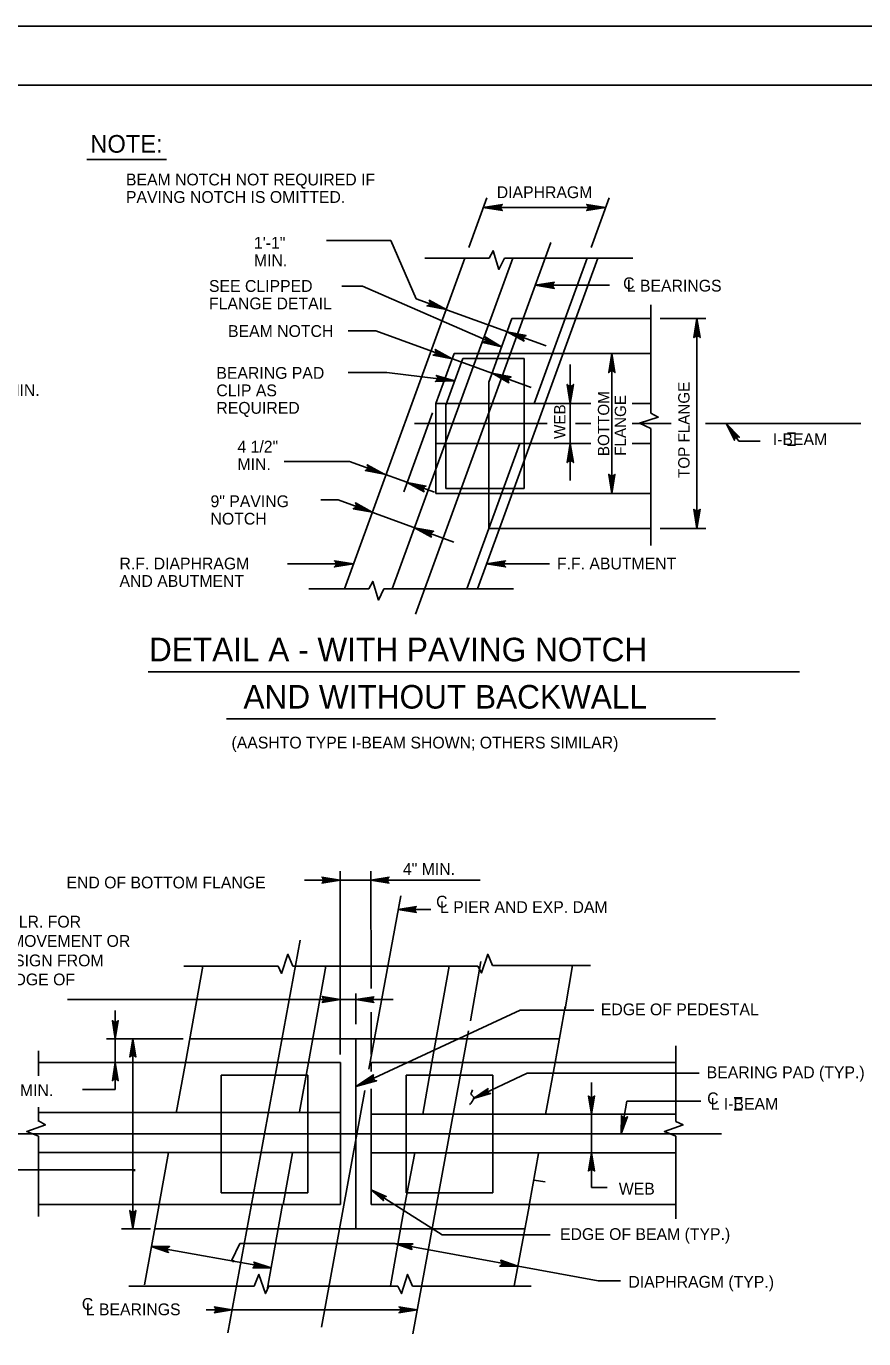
# Model space of a CAD drawing. Extents: x 639028 to 640031, y 298558 to 299746.
# Drawn here: x 639459.6 to 639672.4, y 299412.7 to 299746.3 of the extents above; entities that cross this region are included whole.
import ezdxf

# ---------------------------------------------------------------- set-up
doc = ezdxf.new("R2010")
doc.units = 0
doc.layers.add('1', color=7, linetype='Continuous')
doc.layers.add('PLT-BNDY', color=7, linetype='Continuous')

msp = doc.modelspace()

# ---------------------------------------------------------------- linework, layer by layer
at = {"layer": '1'}
for p, q in [((639067.87, 299731.33), (639853.87, 299731.33)), ((639474.99, 299712.43), (639495.21, 299712.43)), ((639576.61, 299702.74), (639572.01, 299690.11)), ((639607.69, 299702.74), (639603.09, 299690.11)), ((639575.71, 299700.26), (639606.79, 299700.26)), ((639552.19, 299691.84), (639535.85, 299691.84)), ((639558.68, 299677.08), (639552.19, 299691.84)), ((639592.91, 299691.39), (639558.52, 299596.93)), ((639571.02, 299687.39), (639540.43, 299603.33)), ((639583.18, 299687.39), (639552.59, 299603.33)), ((639577.2, 299687.39), (639560.84, 299687.39)), ((639613.7, 299687.39), (639581.08, 299687.39)), ((639602.1, 299687.39), (639596.51, 299672.03)), ((639604.81, 299687.39), (639599.22, 299672.03)), ((639545.05, 299680.29), (639539.8, 299680.29)), ((639580.37, 299664.8), (639545.05, 299680.29)), ((639588.93, 299680.48), (639607.74, 299680.48)), ((639591.71, 299665.06), (639558.68, 299677.08)), ((639618.26, 299675.52), (639618.26, 299647.98)), ((639583, 299672.03), (639577.1, 299655.82)), ((639599.22, 299672.03), (639579.8, 299618.69)), ((639583, 299672.03), (639618.26, 299672.03)), ((639596.51, 299672.03), (639588.66, 299650.44)), ((639620.61, 299672.03), (639632.25, 299672.03)), ((639630, 299672.03), (639630, 299618.69)), ((639548.37, 299668.87), (639541.42, 299668.87)), ((639587.86, 299654.5), (639548.37, 299668.87)), ((639563.65, 299650.44), (639568.28, 299663.14)), ((639566.19, 299649.99), (639570.52, 299661.87)), ((639579.76, 299663.14), (639568.28, 299663.14)), ((639570.52, 299661.87), (639586.11, 299661.87)), ((639579.76, 299663.14), (639618.26, 299663.14)), ((639586.11, 299661.87), (639586.11, 299628.85)), ((639608.37, 299663.14), (639608.37, 299627.58)), ((639551.17, 299658.35), (639541.42, 299658.35)), ((639568.46, 299656.22), (639551.17, 299658.35)), ((639597.82, 299660.36), (639597.82, 299630.83)), ((639577.1, 299655.82), (639577.1, 299618.69)), ((639562.8, 299648.1), (639555.48, 299627.99)), ((639563.65, 299650.44), (639563.65, 299627.58)), ((639563.65, 299650.44), (639577.1, 299650.44)), ((639566.19, 299649.99), (639566.19, 299628.85)), ((639577.1, 299650.44), (639603.04, 299650.44)), ((639613.53, 299650.44), (639618.26, 299650.44)), ((639558.27, 299645.36), (639591.97, 299645.36)), ((639599.13, 299645.36), (639603.04, 299645.36)), ((639613.53, 299645.36), (639623.46, 299645.36)), ((639632.13, 299645.36), (639671.62, 299645.36)), ((639640.66, 299640.86), (639637.53, 299645.23)), ((639618.26, 299644.11), (639618.26, 299614.34)), ((639653.03, 299642.86), (639655.03, 299642.86)), ((639563.65, 299640.28), (639577.1, 299640.28)), ((639577.1, 299640.28), (639603.04, 299640.28)), ((639584.96, 299640.28), (639577.1, 299618.69)), ((639613.53, 299640.28), (639618.26, 299640.28)), ((639640.66, 299640.86), (639646.03, 299640.86)), ((639653.03, 299639.86), (639655.03, 299639.86)), ((639541.73, 299635.71), (639525.15, 299635.71)), ((639563.28, 299627.86), (639541.73, 299635.71)), ((639566.19, 299628.85), (639586.11, 299628.85)), ((639538.85, 299625.93), (639534.43, 299625.93)), ((639568.26, 299615.22), (639538.85, 299625.93)), ((639577.1, 299627.58), (639563.65, 299627.58)), ((639577.1, 299627.58), (639618.26, 299627.58)), ((639577.1, 299618.69), (639571.51, 299603.33)), ((639579.8, 299618.69), (639574.21, 299603.33)), ((639577.1, 299618.69), (639618.26, 299618.69)), ((639620.61, 299618.69), (639632.25, 299618.69)), ((639525.95, 299609.66), (639542.73, 299609.66)), ((639576.52, 299609.66), (639592.52, 299609.66)), ((639546.61, 299603.33), (639531.42, 299603.33)), ((639583.42, 299603.33), (639550.48, 299603.33)), ((639490.55, 299582.26), (639656.07, 299582.26)), ((639510.46, 299570.26), (639634.68, 299570.26)), ((639539.31, 299531.55), (639539.36, 299484.93)), ((639547.16, 299531.56), (639547.19, 299501.72)), ((639530.31, 299529.3), (639574.91, 299529.3)), ((639554.72, 299525.31), (639546.63, 299481.25)), ((639554.09, 299521.81), (639562.34, 299521.81)), ((639529.17, 299514.06), (639510.79, 299414.2)), ((639575.08, 299508.56), (639572.42, 299493.49)), ((639499.59, 299507.43), (639523.59, 299507.43)), ((639504.42, 299507.43), (639500.08, 299482.81)), ((639574.34, 299507.43), (639527.34, 299507.43)), ((639535.72, 299507.43), (639531.27, 299482.93)), ((639567.06, 299507.43), (639562.63, 299482.93)), ((639602.97, 299507.56), (639578.09, 299507.56)), ((639598.34, 299507.56), (639596.47, 299496.56)), ((639470.08, 299498.93), (639539.35, 299498.93)), ((639539.35, 299498.93), (639552.83, 299498.93)), ((639543.34, 299500.44), (639543.34, 299492.65)), ((639482.22, 299488.93), (639482.22, 299496.14)), ((639585.05, 299496.22), (639543.34, 299476.79)), ((639547.2, 299495.74), (639547.21, 299484.94)), ((639585.05, 299496.22), (639603.8, 299496.22)), ((639596.47, 299497.18), (639593.93, 299482.93)), ((639479.95, 299488.93), (639499.47, 299488.93)), ((639482.22, 299482.81), (639482.22, 299488.93)), ((639486.66, 299440.68), (639486.66, 299488.93)), ((639532.47, 299488.93), (639501.16, 299488.93)), ((639532.47, 299488.93), (639563.71, 299488.93)), ((639543.34, 299440.68), (639543.34, 299488.93)), ((639571.93, 299490.95), (639557.77, 299413.94)), ((639563.71, 299488.93), (639594.97, 299488.93)), ((639462.72, 299485.93), (639462.72, 299479.56)), ((639624.59, 299487.18), (639624.59, 299467.93)), ((639462.72, 299482.93), (639539.47, 299482.93)), ((639482.22, 299476.09), (639482.22, 299482.81)), ((639500.08, 299482.81), (639497.68, 299470.06)), ((639529, 299470.43), (639531.27, 299482.93)), ((639539.47, 299446.81), (639539.47, 299482.93)), ((639547.22, 299482.93), (639624.59, 299482.93)), ((639547.22, 299480.6), (639547.22, 299482.93)), ((639562.63, 299482.93), (639560.36, 299469.81)), ((639593.93, 299482.93), (639591.52, 299469.68)), ((639531.11, 299479.68), (639509.11, 299479.68)), ((639509.11, 299479.68), (639509.11, 299449.81)), ((639531.11, 299449.81), (639531.11, 299479.68)), ((639556.12, 299479.68), (639578.12, 299479.68)), ((639556.12, 299449.81), (639556.12, 299479.68)), ((639586.88, 299480.18), (639573.19, 299473.8)), ((639578.12, 299479.68), (639578.12, 299449.81)), ((639586.88, 299480.18), (639630.59, 299480.18)), ((639473.85, 299476.09), (639482.22, 299476.09)), ((639545.64, 299475.83), (639534.59, 299415.68)), ((639547.22, 299446.81), (639547.22, 299476.2)), ((639603.22, 299477.82), (639603.22, 299451.14)), ((639462.72, 299471.59), (639462.72, 299467.93)), ((639612.22, 299473.06), (639610.72, 299464.81)), ((639612.22, 299473.06), (639630.97, 299473.06)), ((639639.47, 299473.93), (639641.47, 299473.93)), ((639539.47, 299470.18), (639462.72, 299470.18)), ((639624.59, 299469.81), (639547.22, 299469.81)), ((639639.47, 299470.93), (639641.47, 299470.93)), ((639454.72, 299464.81), (639520.11, 299464.81)), ((639520.11, 299464.81), (639543.61, 299464.81)), ((639543.61, 299464.81), (639567.12, 299464.81)), ((639567.12, 299464.81), (639636.22, 299464.81)), ((639462.72, 299464.18), (639462.72, 299443.81)), ((639624.59, 299464.18), (639624.59, 299443.15)), ((639539.47, 299460.06), (639462.72, 299460.06)), ((639493.35, 299446.93), (639495.73, 299460.06)), ((639524.84, 299446.81), (639527.22, 299459.93)), ((639624.59, 299459.93), (639547.22, 299459.93)), ((639555.81, 299446.81), (639558.33, 299459.93)), ((639589.74, 299459.81), (639587.43, 299447.06)), ((639434.55, 299455.68), (639486.66, 299455.68)), ((639588.59, 299453.06), (639591.47, 299452.56)), ((639509.11, 299449.81), (639531.11, 299449.81)), ((639547.22, 299450.53), (639565.3, 299439.12)), ((639578.12, 299449.81), (639556.12, 299449.81)), ((639603.22, 299451.14), (639607.2, 299451.14)), ((639539.47, 299446.81), (639462.72, 299446.81)), ((639493.33, 299446.81), (639489.67, 299426.43)), ((639524.68, 299446.81), (639520.82, 299425.15)), ((639624.59, 299446.81), (639547.22, 299446.81)), ((639555.81, 299446.81), (639552.1, 299426.18)), ((639587.44, 299446.81), (639583.59, 299426.18)), ((639483.79, 299440.68), (639491.13, 299440.68)), ((639523.59, 299440.68), (639492.23, 299440.68)), ((639554.71, 299440.68), (639523.59, 299440.68)), ((639586.3, 299440.68), (639554.71, 299440.68)), ((639565.3, 299439.12), (639592.68, 299439.12)), ((639491.36, 299436.14), (639521.77, 299430.71)), ((639513.84, 299436.93), (639511.77, 299432.5)), ((639513.84, 299436.93), (639553.09, 299436.93)), ((639553.16, 299436.95), (639604.86, 299427.41)), ((639485.63, 299426.06), (639517.47, 299426.06)), ((639521.22, 299426.06), (639553.97, 299426.06)), ((639587.84, 299426.06), (639557.72, 299426.06)), ((639604.86, 299427.41), (639610.58, 299427.41)), ((639505.34, 299420.06), (639511.87, 299420.06)), ((639511.87, 299420.06), (639558.9, 299420.06))]:
    msp.add_line(p, q, dxfattribs=at)
for points in [[(639580.32, 299699.69), (639580.15, 299700.02), (639575.71, 299700.26), (639580.32, 299699.69), (639580.56, 299699.48), (639575.71, 299700.26), (639580.14, 299700.48), (639580.31, 299700.81), (639575.71, 299700.26), (639580.56, 299701.03), (639580.31, 299700.81)], [(639602.18, 299699.69), (639602.35, 299700.02), (639606.79, 299700.26), (639602.18, 299699.69), (639601.94, 299699.48), (639606.79, 299700.26), (639602.35, 299700.48), (639602.19, 299700.81), (639606.79, 299700.26), (639601.94, 299701.03), (639602.19, 299700.81)], [(639581.08, 299687.39), (639579.7, 299684.51), (639578.2, 299689.26), (639577.2, 299687.39)], [(639593.55, 299679.9), (639593.37, 299680.23), (639588.93, 299680.48), (639593.55, 299679.9), (639593.78, 299679.7), (639588.93, 299680.48), (639593.37, 299680.7), (639593.53, 299681.03), (639588.93, 299680.48), (639593.78, 299681.25), (639593.53, 299681.03)], [(639561.73, 299675.35), (639562.01, 299675.61), (639566.26, 299674.32), (639561.73, 299675.35), (639561.44, 299675.25), (639566.26, 299674.32), (639562.17, 299676.05), (639562.13, 299676.41), (639566.26, 299674.32), (639561.97, 299676.7), (639562.13, 299676.41)], [(639629.42, 299667.42), (639629.76, 299667.59), (639630, 299672.03), (639629.42, 299667.42), (639629.22, 299667.18), (639630, 299672.03), (639630.22, 299667.59), (639630.55, 299667.43), (639630, 299672.03), (639630.77, 299667.18), (639630.55, 299667.43)], [(639586.31, 299667.64), (639586.03, 299667.39), (639581.78, 299668.67), (639586.31, 299667.64), (639586.6, 299667.75), (639581.78, 299668.67), (639585.87, 299666.95), (639585.91, 299666.58), (639581.78, 299668.67), (639586.07, 299666.29), (639585.91, 299666.58)], [(639575.89, 299666.07), (639576.18, 299666.31), (639580.37, 299664.8), (639575.89, 299666.07), (639575.6, 299665.97), (639580.37, 299664.8), (639576.37, 299666.73), (639576.35, 299667.1), (639580.37, 299664.8), (639576.2, 299667.4), (639576.35, 299667.1)], [(639563.26, 299662.84), (639563.53, 299663.09), (639567.79, 299661.8), (639563.26, 299662.84), (639562.96, 299662.73), (639567.79, 299661.8), (639563.69, 299663.53), (639563.65, 299663.89), (639567.79, 299661.8), (639563.5, 299664.19), (639563.65, 299663.89)], [(639607.79, 299658.53), (639608.12, 299658.7), (639608.37, 299663.14), (639607.79, 299658.53), (639607.58, 299658.29), (639608.37, 299663.14), (639608.59, 299658.7), (639608.92, 299658.54), (639608.37, 299663.14), (639609.14, 299658.29), (639608.92, 299658.54)], [(639582.47, 299657.08), (639582.19, 299656.82), (639577.93, 299658.11), (639582.47, 299657.08), (639582.76, 299657.19), (639577.93, 299658.11), (639582.03, 299656.39), (639582.07, 299656.02), (639577.93, 299658.11), (639582.23, 299655.73), (639582.07, 299656.02)], [(639563.81, 299656.21), (639564.02, 299656.52), (639568.46, 299656.22), (639563.81, 299656.21), (639563.55, 299656.04), (639568.46, 299656.22), (639564.08, 299656.98), (639563.96, 299657.33), (639568.46, 299656.22), (639563.74, 299657.58), (639563.96, 299657.33)], [(639598.4, 299655.05), (639598.07, 299654.88), (639597.82, 299650.44), (639598.4, 299655.05), (639598.6, 299655.29), (639597.82, 299650.44), (639597.6, 299654.88), (639597.27, 299655.04), (639597.82, 299650.44), (639597.05, 299655.29), (639597.27, 299655.04)], [(639618.26, 299644.11), (639615.39, 299645.48), (639620.14, 299646.98), (639618.26, 299647.98)], [(639639.53, 299641.36), (639639.78, 299641.61), (639637.53, 299645.23), (639639.53, 299641.36), (639639.53, 299641.11), (639637.53, 299645.23), (639640.16, 299641.86), (639640.41, 299641.98), (639637.53, 299645.23), (639640.78, 299641.86), (639640.41, 299641.98)], [(639597.24, 299635.67), (639597.58, 299635.84), (639597.82, 299640.28), (639597.24, 299635.67), (639597.04, 299635.43), (639597.82, 299640.28), (639598.04, 299635.84), (639598.37, 299635.68), (639597.82, 299640.28), (639598.59, 299635.43), (639598.37, 299635.68)], [(639546.01, 299633.53), (639546.28, 299633.79), (639550.54, 299632.5), (639546.01, 299633.53), (639545.71, 299633.43), (639550.54, 299632.5), (639546.44, 299634.22), (639546.4, 299634.59), (639550.54, 299632.5), (639546.24, 299634.88), (639546.4, 299634.59)], [(639608.94, 299632.19), (639608.61, 299632.02), (639608.37, 299627.58), (639608.94, 299632.19), (639609.15, 299632.43), (639608.37, 299627.58), (639608.15, 299632.02), (639607.82, 299632.18), (639608.37, 299627.58), (639607.6, 299632.43), (639607.82, 299632.18)], [(639560.89, 299629.35), (639560.61, 299629.1), (639556.35, 299630.38), (639560.89, 299629.35), (639561.18, 299629.46), (639556.35, 299630.38), (639560.45, 299628.66), (639560.49, 299628.29), (639556.35, 299630.38), (639560.65, 299628), (639560.49, 299628.29)], [(639542.97, 299623.81), (639543.25, 299624.07), (639547.5, 299622.78), (639542.97, 299623.81), (639542.68, 299623.7), (639547.5, 299622.78), (639543.41, 299624.5), (639543.37, 299624.87), (639547.5, 299622.78), (639543.21, 299625.16), (639543.37, 299624.87)], [(639630.58, 299623.3), (639630.25, 299623.13), (639630, 299618.69), (639630.58, 299623.3), (639630.78, 299623.54), (639630, 299618.69), (639629.78, 299623.13), (639629.45, 299623.29), (639630, 299618.69), (639629.23, 299623.54), (639629.45, 299623.29)], [(639562.78, 299617.84), (639562.5, 299617.58), (639558.24, 299618.87), (639562.78, 299617.84), (639563.07, 299617.95), (639558.24, 299618.87), (639562.34, 299617.15), (639562.38, 299616.78), (639558.24, 299618.87), (639562.54, 299616.49), (639562.38, 299616.78)], [(639538.12, 299609.08), (639538.29, 299609.42), (639542.73, 299609.66), (639538.12, 299609.08), (639537.88, 299608.88), (639542.73, 299609.66), (639538.29, 299609.88), (639538.13, 299610.21), (639542.73, 299609.66), (639537.88, 299610.43), (639538.13, 299610.21)], [(639581.13, 299609.08), (639580.96, 299609.42), (639576.52, 299609.66), (639581.13, 299609.08), (639581.37, 299608.88), (639576.52, 299609.66), (639580.95, 299609.88), (639581.12, 299610.21), (639576.52, 299609.66), (639581.37, 299610.43), (639581.12, 299610.21)], [(639550.48, 299603.33), (639549.11, 299600.46), (639547.61, 299605.21), (639546.61, 299603.33)], [(639534.94, 299529.8), (639535.06, 299529.55), (639539.31, 299529.3), (639534.94, 299529.8), (639534.69, 299530.05), (639539.31, 299529.3), (639535.06, 299529.05), (639534.94, 299528.8), (639539.31, 299529.3), (639534.69, 299528.55), (639534.94, 299528.8)], [(639551.54, 299528.8), (639551.41, 299529.05), (639547.16, 299529.3), (639551.54, 299528.8), (639551.79, 299528.55), (639547.16, 299529.3), (639551.41, 299529.55), (639551.54, 299529.8), (639547.16, 299529.3), (639551.79, 299530.05), (639551.54, 299529.8)], [(639558.47, 299521.31), (639558.34, 299521.56), (639554.09, 299521.81), (639558.47, 299521.31), (639558.72, 299521.06), (639554.09, 299521.81), (639558.34, 299522.06), (639558.47, 299522.31), (639554.09, 299521.81), (639558.72, 299522.56), (639558.47, 299522.31)], [(639527.34, 299507.43), (639526.09, 299510.43), (639524.47, 299505.56), (639523.59, 299507.43)], [(639578.09, 299507.56), (639576.84, 299510.43), (639575.22, 299505.68), (639574.34, 299507.43)], [(639534.95, 299499.5), (639535.13, 299499.15), (639539.35, 299498.93), (639534.95, 299499.5), (639534.79, 299499.73), (639539.35, 299498.93), (639535.19, 299498.78), (639534.99, 299498.49), (639539.35, 299498.93), (639534.78, 299498.21), (639534.99, 299498.49)], [(639547.77, 299498.31), (639547.58, 299498.66), (639543.34, 299498.93), (639547.77, 299498.31), (639547.91, 299498.21), (639543.34, 299498.93), (639547.62, 299499.17), (639547.7, 299499.44), (639543.34, 299498.93), (639547.92, 299499.6), (639547.7, 299499.44)], [(639482.72, 299493.31), (639482.47, 299493.18), (639482.22, 299488.93), (639482.72, 299493.31), (639482.97, 299493.56), (639482.22, 299488.93), (639481.97, 299493.18), (639481.72, 299493.31), (639482.22, 299488.93), (639481.47, 299493.56), (639481.72, 299493.31)], [(639486.16, 299484.56), (639486.41, 299484.68), (639486.66, 299488.93), (639486.16, 299484.56), (639485.91, 299484.31), (639486.66, 299488.93), (639486.91, 299484.68), (639487.16, 299484.56), (639486.66, 299488.93), (639487.41, 299484.31), (639487.16, 299484.56)], [(639481.72, 299478.56), (639481.97, 299478.68), (639482.22, 299482.93), (639481.72, 299478.56), (639481.47, 299478.31), (639482.22, 299482.93), (639482.47, 299478.68), (639482.72, 299478.56), (639482.22, 299482.93), (639482.97, 299478.31), (639482.72, 299478.56)], [(639548.3, 299478.29), (639547.99, 299478.59), (639543.34, 299476.79), (639548.3, 299478.29), (639548.59, 299478.29), (639543.34, 299476.79), (639547.7, 299479.04), (639547.7, 299479.49), (639543.34, 299476.79), (639547.84, 299479.79), (639547.7, 299479.49)], [(639577.31, 299475.05), (639577.06, 299475.3), (639573.19, 299473.8), (639577.31, 299475.05), (639577.56, 299475.05), (639573.19, 299473.8), (639576.81, 299475.68), (639576.81, 299476.05), (639573.19, 299473.8), (639576.94, 299476.3), (639576.81, 299476.05)], [(639603.72, 299474.18), (639603.47, 299474.06), (639603.22, 299469.81), (639603.72, 299474.18), (639603.97, 299474.43), (639603.22, 299469.81), (639602.97, 299474.06), (639602.72, 299474.18), (639603.22, 299469.81), (639602.47, 299474.43), (639602.72, 299474.18)], [(639462.72, 299464.18), (639459.72, 299465.43), (639464.47, 299467.06), (639462.72, 299468.06)], [(639612.09, 299468.93), (639611.72, 299468.81), (639610.72, 299464.81), (639612.09, 299468.93), (639612.34, 299469.18), (639610.72, 299464.81), (639611.34, 299468.93), (639611.09, 299469.18), (639610.72, 299464.81), (639610.84, 299469.43), (639611.09, 299469.18)], [(639624.59, 299464.18), (639621.72, 299465.43), (639626.47, 299467.06), (639624.59, 299467.93)], [(639602.72, 299455.56), (639602.97, 299455.68), (639603.22, 299459.93), (639602.72, 299455.56), (639602.47, 299455.31), (639603.22, 299459.93), (639603.47, 299455.68), (639603.72, 299455.56), (639603.22, 299459.93), (639603.97, 299455.31), (639603.72, 299455.56)], [(639550.27, 299448.02), (639550.3, 299448.34), (639547.22, 299450.53), (639550.27, 299448.02), (639550.35, 299447.77), (639547.22, 299450.53), (639550.51, 299448.67), (639550.78, 299448.84), (639547.22, 299450.53), (639551.06, 299448.88), (639550.78, 299448.84)], [(639487.16, 299445.06), (639486.91, 299444.93), (639486.66, 299440.68), (639487.16, 299445.06), (639487.41, 299445.31), (639486.66, 299440.68), (639486.41, 299444.93), (639486.16, 299445.06), (639486.66, 299440.68), (639485.91, 299445.31), (639486.16, 299445.06)], [(639495.49, 299434.89), (639495.49, 299435.26), (639491.36, 299436.14), (639495.49, 299434.89), (639495.74, 299434.64), (639491.36, 299436.14), (639495.49, 299435.64), (639495.74, 299435.89), (639491.36, 299436.14), (639495.99, 299436.14), (639495.74, 299435.89)], [(639557.47, 299435.68), (639557.34, 299435.93), (639553.22, 299436.93), (639557.47, 299435.68), (639557.59, 299435.43), (639553.22, 299436.93), (639557.34, 299436.43), (639557.59, 299436.68), (639553.22, 299436.93), (639557.84, 299436.81), (639557.59, 299436.68)], [(639517.56, 299431.96), (639517.68, 299431.58), (639521.81, 299430.71), (639517.56, 299431.96), (639517.43, 299432.21), (639521.81, 299430.71), (639517.56, 299431.21), (639517.43, 299430.96), (639521.81, 299430.71), (639517.18, 299430.71), (639517.43, 299430.96)], [(639580.27, 299432.41), (639580.4, 299432.04), (639584.52, 299431.16), (639580.27, 299432.41), (639580.15, 299432.66), (639584.52, 299431.16), (639580.4, 299431.66), (639580.15, 299431.41), (639584.52, 299431.16), (639579.9, 299431.16), (639580.15, 299431.41)], [(639517.47, 299426.06), (639518.72, 299429.06), (639520.34, 299424.18), (639521.22, 299426.06)], [(639557.72, 299426.06), (639556.47, 299429.06), (639554.97, 299424.18), (639553.97, 299426.06)], [(639507.62, 299420.56), (639507.75, 299420.31), (639511.87, 299420.06), (639507.62, 299420.56), (639507.37, 299420.81), (639511.87, 299420.06), (639507.75, 299419.81), (639507.62, 299419.56), (639511.87, 299420.06), (639507.37, 299419.31), (639507.62, 299419.56)], [(639554.52, 299420.56), (639554.77, 299420.31), (639558.9, 299420.06), (639554.52, 299420.56), (639554.27, 299420.81), (639558.9, 299420.06), (639554.77, 299419.81), (639554.52, 299419.56), (639558.9, 299420.06), (639554.27, 299419.31), (639554.52, 299419.56)]]:
    msp.add_lwpolyline(points, dxfattribs=at)
msp.add_spline([(639572.96, 299476), (639572.83, 299475.5), (639572.58, 299475.13), (639572.71, 299474.75), (639573.08, 299474.38), (639573.33, 299474), (639573.08, 299473.38), (639572.71, 299472.75), (639572.21, 299472.25)], degree=3, dxfattribs=at)
at = {"layer": 'PLT-BNDY'}
msp.add_lwpolyline([(639027.87, 299746.33), (639868.87, 299746.33), (639868.87, 299152.33), (639027.87, 299152.33)], close=True, dxfattribs=at)

# ---------------------------------------------------------------- texts
at = {"layer": '1'}
for s, height, p in [('NOTE: ', 4.5, (639475.86, 299714.18)), ('BEAM NOTCH NOT REQUIRED IF', 3, (639484.92, 299705.87)), ('DIAPHRAGM', 3, (639579.13, 299702.64)), ('PAVING NOTCH IS OMITTED.', 3, (639484.92, 299701.43)), ('1\'-1"', 3, (639517.44, 299689.78)), ('MIN.', 3, (639517.44, 299685.34)), ('SEE CLIPPED', 3, (639506.02, 299678.81)), ('C', 3, (639611.24, 299679.49)), ('L BEARINGS', 3, (639612.17, 299678.89)), ('FLANGE DETAIL', 3, (639506.02, 299674.37)), ('BEAM NOTCH', 3, (639510.86, 299667.35)), ('BEARING PAD', 3, (639507.89, 299656.71)), ('1\'-2" MIN.', 3, (639445.43, 299652.35)), ('CLIP AS', 3, (639507.89, 299652.27)), ('REQUIRED', 3, (639507.89, 299647.83)), ('  I-BEAM', 3, (639647.03, 299639.86)), ('4 1/2"', 3, (639513.25, 299637.96)), ('MIN.', 3, (639513.25, 299633.52)), ('9" PAVING', 3, (639506.41, 299624.09)), ('NOTCH', 3, (639506.41, 299619.65)), ('R.F. DIAPHRAGM', 3, (639483.28, 299608.26)), ('F.F. ABUTMENT', 3, (639594.42, 299608.26)), ('AND ABUTMENT', 3, (639483.28, 299603.82)), ('DETAIL A - WITH PAVING NOTCH', 6, (639490.77, 299584.9)), ('AND WITHOUT BACKWALL', 6, (639514.77, 299572.89)), ('(AASHTO TYPE I-BEAM SHOWN; OTHERS SIMILAR)', 3, (639511.73, 299562.75)), ('4" MIN.', 3, (639555.29, 299530.61)), ('END OF BOTTOM FLANGE', 3, (639469.81, 299527.18)), ('C', 3, (639563.72, 299522.31)), ('L PIER AND EXP. DAM', 3, (639564.72, 299520.93)), ('PROVIDE MIN.OF 2" CLR. FOR', 3, (639415.7, 299517.23)), ('ANTICIPATED BEAM MOVEMENT OR', 3, (639415.59, 299512.32)), ('AS REQUIRED BY DESIGN FROM', 3, (639415.7, 299507.37)), ('EDGE OF BEAM TO EDGE OF', 3, (639415.59, 299502.54)), ('EDGE OF PEDESTAL', 3, (639605.57, 299494.93)), ('BEARING PAD (TYP.)', 3, (639632.47, 299478.93)), ('2" MIN.', 3, (639453.22, 299474.39)), ('C', 3, (639632.59, 299472.31)), ('L I-BEAM', 3, (639633.47, 299470.93)), ('.', 3.85, (639486.32, 299455.27)), ('WEB', 3, (639610.14, 299449.35)), ('EDGE OF BEAM (TYP.)', 3, (639595.2, 299437.81)), ('.', 3.85, (639511.47, 299432.11)), ('DIAPHRAGM (TYP.)', 3, (639612.57, 299425.68)), ('C', 3, (639473.72, 299420.06)), ('L BEARINGS', 3, (639474.72, 299418.68))]:
    msp.add_text(s, height=height, dxfattribs=at).set_placement(p)
for s, p in [('TOP FLANGE', (639628.12, 299631.52)), ('BOTTOM', (639607.71, 299637.07)), ('FLANGE', (639611.98, 299637.15)), ('WEB', (639596.58, 299641.43))]:
    msp.add_text(s, height=2.886, rotation=90, dxfattribs=at).set_placement(p)

doc.saveas('drawing.dxf')
